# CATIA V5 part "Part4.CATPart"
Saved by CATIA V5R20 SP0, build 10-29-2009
Part number: Part4
Bounding box of the stored display mesh (mm): x 163.165 to 179.687, y 63.417 to 71.037, z 93.618 to 175.159
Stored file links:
  C:\Users\Orange\Desktop\Assembly Design-19\Part4.CATPart
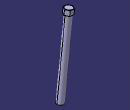
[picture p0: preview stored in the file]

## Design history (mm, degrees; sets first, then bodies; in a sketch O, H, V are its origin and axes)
Body1 (main body)
  DatumSurface1
  Sketch1 on face of DatumSurface1, origin (342.8423, 0, 194.0974), H (-0.994, 0, -0.1096), V (0, 1, 0)
    circle A1 centre (176.4046, 67.227) radius 3.302
    line L1 (178.6043, 71.037) -> (174.2049, 71.037)
    line L2 (174.2049, 71.037) -> (172.0051, 67.227)
    line L3 (172.0051, 67.227) -> (174.2049, 63.417)
    line L4 (174.2049, 63.417) -> (178.6043, 63.417)
    line L5 (178.6043, 63.417) -> (180.804, 67.227)
    line L6 (180.804, 67.227) -> (178.6043, 71.037)
    construction line L7 (176.4046, 67.227) -> (176.4046, 71.037)
    radius A1 = 3.302
    distance L1 L4 = 7.62
  Pad1: profile Sketch1.L3, length 5.08
  Pad2: profile Sketch1.A1, length 81.28
  Plane1: type 3Points, Element1 vertex [face of Pad1 from Sketch1.L1 | face of Pad2 | face of Pad1 from Sketch1.L2], Element2 vertex [face of Pad1 from Sketch1.L5 | face of Pad2 | face of Pad1 from Sketch1.L4], Element3 vertex [face of Pad1 from Sketch1.L4 | face of Pad1 from Sketch1.L5 | end face of Pad1]
  Sketch2 on Plane1, origin (109.4562, -63.5773, 12.0645), H (0.5023, 0.8647, 0), V (-0.082, 0.0477, 0.9955)
    projected line E1 (146.6542, 163.6856) -> (144.4578, 163.5646) from edge [face of Pad2 | face of Pad1 from Sketch1.L2]
    projected line E2 (146.6542, 163.6856) -> (145.7663, 163.6367) from edge [face of Pad2 | face of Pad1 from Sketch1.L2]
    point P1 (146.6542, 163.6856)
    projected line E3 (146.6542, 163.6856) -> (146.9337, 158.6133) from edge [face of Pad1 from Sketch1.L2 | face of Pad1 from Sketch1.L1]
    projected line E4 (146.6542, 163.6856) -> (146.6736, 163.334) from edge [face of Pad1 from Sketch1.L2 | face of Pad1 from Sketch1.L1]
    point P3 (146.6542, 163.6856)
    arc A1 centre (145.8378, 162.3399) radius 1.2988 from (145.7663, 163.6367) to (146.6736, 163.334) cw
    point P6 (145.7663, 163.6367)
    point P7 (146.6736, 163.334)
    coincidence: P6 E1, P7 E3, P1 P3
    tangency: A1 E1
  Groove1: profile Sketch2, axis axis of face of Pad2 from Sketch1.A1, angle 360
